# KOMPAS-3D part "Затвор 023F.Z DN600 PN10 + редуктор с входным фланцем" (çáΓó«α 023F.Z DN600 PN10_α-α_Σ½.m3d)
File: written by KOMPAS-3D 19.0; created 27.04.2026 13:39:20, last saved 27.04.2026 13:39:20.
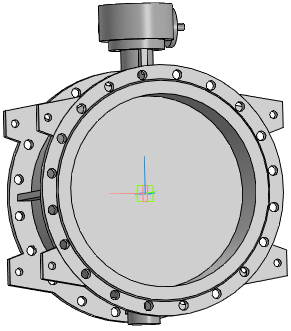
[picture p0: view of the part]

Document properties: Полное имя файла: ..\..\Затвор 023F.Z DN200-DN1600_редуктор с входным фланцем\Затвор 023F.Z DN600 PN10 + редуктор с входным фланцем.a3d

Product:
- Part/product: Затвор 023F.Z DN600 PN10 + редуктор с входным фланцем
    Масса: 386.006

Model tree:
1. Операция без истории:1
